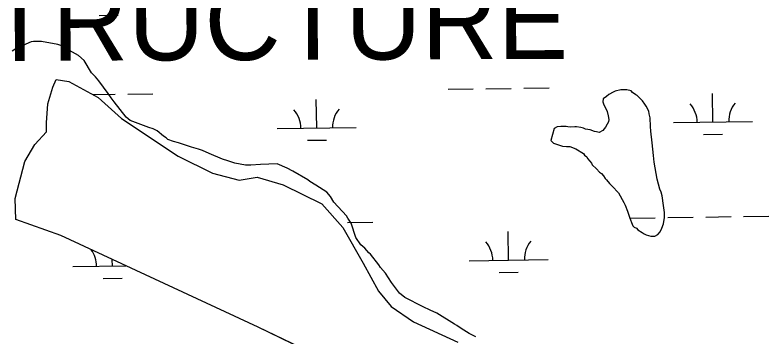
# Model space of a CAD drawing. Extents: x 3807117 to 3845308, y 337856 to 363736.
# Drawn here: x 3834347 to 3835302, y 345281 to 345688 of the extents above; entities that cross this region are included whole.
import ezdxf

# ---------------------------------------------------------------- set-up
doc = ezdxf.new("R2010")
doc.units = 0
for name, color, linetype in [('V-RIVR-IDEN', 7, 'Continuous'), ('V-SITE-VEGE', 7, 'Continuous'), ('V-TOPO-SHOR', 7, 'Continuous'), ('V-WETL-SWMP', 7, 'Continuous')]:
    doc.layers.add(name, color=color, linetype=linetype)

msp = doc.modelspace()

# ---------------------------------------------------------------- linework, layer by layer
at = {"layer": 'V-SITE-VEGE'}
for points in [[(3834698.71, 345490.65), (3834691.33, 345494.32), (3834678.88, 345499.83), (3834657.68, 345499.34), (3834645.69, 345498.4), (3834638.78, 345498.39), (3834625.41, 345500.67), (3834616.19, 345503.89), (3834609.73, 345505.72), (3834592.67, 345513.07), (3834584.36, 345516.74), (3834579.29, 345518.58), (3834570.53, 345520.87), (3834553.93, 345526.38), (3834547.47, 345528.21), (3834540.56, 345530.97), (3834538.25, 345532.8), (3834535.02, 345535.1), (3834526.71, 345541.54), (3834521.64, 345544.3), (3834516.1, 345546.14), (3834492.59, 345554.86), (3834487.51, 345559), (3834472.27, 345578.34), (3834468.58, 345583.4), (3834464.88, 345588.92), (3834452.87, 345605.04), (3834448.71, 345610.1), (3834443.64, 345615.16), (3834434.39, 345630.82), (3834427.01, 345637.26), (3834411.79, 345645.53), (3834407.17, 345648.75), (3834401.18, 345651.05), (3834380.43, 345654.7), (3834370.29, 345654.69), (3834367.07, 345654.22), (3834349.1, 345646.36), (3834343.12, 345642.66)], [(3834930.41, 345280.83), (3834922.1, 345285.42), (3834911.95, 345291.4), (3834906.42, 345295.54), (3834903.65, 345296.91), (3834881.04, 345311.17), (3834872.74, 345314.85), (3834863.98, 345318.98), (3834840.45, 345330.93), (3834833.99, 345336.45), (3834823.83, 345349.8), (3834815.98, 345361.77), (3834809.97, 345368.67), (3834807.66, 345372.36), (3834797.04, 345385.71), (3834795.2, 345387.55), (3834790.12, 345393.07), (3834785.04, 345397.67), (3834778.57, 345406.88), (3834772.55, 345424.85), (3834768.4, 345431.29), (3834766.55, 345434.06), (3834750.85, 345451.55), (3834746.23, 345458.45), (3834741.62, 345463.98), (3834727.77, 345473.18), (3834720.39, 345477.77), (3834717.62, 345479.61), (3834698.71, 345490.65)]]:
    msp.add_lwpolyline(points, dxfattribs=at)
msp.add_lwpolyline([(3835025.43, 345529.4), (3835029.12, 345526.18), (3835036.5, 345523.43), (3835040.19, 345522.51), (3835045.26, 345522.06), (3835049.41, 345522.06), (3835057.25, 345518.85), (3835066.94, 345512.87), (3835068.33, 345511.03), (3835071.09, 345508.73), (3835072.02, 345506.89), (3835074.79, 345503.2), (3835077.1, 345500.9), (3835078.02, 345498.6), (3835083.56, 345493.54), (3835087.25, 345489.4), (3835089.56, 345487.55), (3835092.33, 345484.79), (3835094.18, 345481.57), (3835096.03, 345479.73), (3835099.72, 345475.13), (3835103.41, 345471.91), (3835111.26, 345463.16), (3835118.19, 345451.19), (3835119.58, 345447.5), (3835122.82, 345440.13), (3835125.6, 345431.38), (3835128.38, 345423.55), (3835129.3, 345421.71), (3835131.15, 345419.87), (3835133.92, 345418.49), (3835135.76, 345416.65), (3835141.3, 345412.97), (3835143.61, 345411.59), (3835146.37, 345410.21), (3835152.37, 345408.38), (3835157.44, 345408.38), (3835161.12, 345410.69), (3835163.88, 345413.93), (3835166.18, 345418.54), (3835168.48, 345424.07), (3835169.39, 345431.91), (3835169.38, 345438.36), (3835168.44, 345447.12), (3835166.58, 345459.56), (3835165.19, 345464.16), (3835163.8, 345467.85), (3835160.09, 345480.75), (3835156.37, 345501.95), (3835155.44, 345510.7), (3835154.03, 345526.37), (3835152.16, 345541.12), (3835151.69, 345547.11), (3835151.22, 345558.17), (3835150.29, 345563.24), (3835149.82, 345566.47), (3835146.12, 345572.91), (3835144.74, 345575.67), (3835141.5, 345579.82), (3835135.04, 345586.26), (3835133.2, 345587.18), (3835129.04, 345590.4), (3835127.2, 345592.24), (3835121.66, 345593.61), (3835114.29, 345593.6), (3835106.92, 345591.75), (3835104.62, 345590.82), (3835099.09, 345587.59), (3835095.87, 345585.28), (3835091.72, 345582.05), (3835091.27, 345578.36), (3835092.19, 345576.06), (3835096.82, 345566.38), (3835098.21, 345560.85), (3835099.14, 345556.24), (3835098.68, 345553.02), (3835096.84, 345550.25), (3835095, 345546.56), (3835091.32, 345541.95), (3835086.72, 345539.63), (3835083.49, 345540.55), (3835080.72, 345541.01), (3835075.19, 345542.84), (3835069.66, 345543.76), (3835066.89, 345545.14), (3835063.66, 345546.05), (3835058.13, 345546.97), (3835055.83, 345546.96), (3835050.3, 345546.49), (3835047.07, 345546.95), (3835044.76, 345547.41), (3835038.31, 345547.4), (3835033.7, 345546.93), (3835029.56, 345544.62)], close=True, dxfattribs=at)
at = {"layer": 'V-TOPO-SHOR'}
msp.add_lwpolyline([(3834740.93, 345251.84), (3834654.87, 345293.38), (3834404.69, 345409.13), (3834347.92, 345429.43), (3834347, 345456.03), (3834359.34, 345503.03), (3834371.71, 345524.33), (3834386.76, 345540.31), (3834386.75, 345551.83), (3834388.48, 345575.77), (3834394.65, 345597.06), (3834399.07, 345606.82), (3834415.03, 345604.18), (3834452.3, 345583.85), (3834481.59, 345557.3), (3834553.48, 345509.54), (3834596.95, 345488.32), (3834630.65, 345479.51), (3834653.69, 345483.09), (3834686.51, 345473.39), (3834735.3, 345449.53), (3834761.95, 345419.43), (3834787.73, 345374.26), (3834807.28, 345338.82), (3834823.27, 345319.35), (3834851.67, 345299.89), (3834907.56, 345274.26)], dxfattribs=at)
at = {"layer": 'V-WETL-SWMP'}
for p, q in [((3834453.42, 345687.66), (3834477.42, 345688.02)), ((3834394.65, 345597.06), (3834399.07, 345606.82)), ((3834399.07, 345606.82), (3834415.03, 345604.18)), ((3834415.03, 345604.18), (3834452.3, 345583.85)), ((3834388.48, 345575.77), (3834394.65, 345597.06)), ((3834895.37, 345594.27), (3834927.37, 345594.75)), ((3834943.36, 345594.99), (3834975.36, 345595.47)), ((3834991.36, 345595.71), (3835023.35, 345596.19)), ((3834445.55, 345587.53), (3834473.51, 345587.95)), ((3834452.3, 345583.85), (3834481.59, 345557.3)), ((3834489.51, 345588.19), (3834521.5, 345588.67)), ((3834729.02, 345545.34), (3834728.48, 345581.34)), ((3835230.87, 345552.86), (3835230.33, 345588.86)), ((3834386.74, 345551.83), (3834388.48, 345575.77)), ((3834481.59, 345557.3), (3834553.48, 345509.53)), ((3835180.88, 345552.11), (3835280.87, 345553.61)), ((3834386.76, 345540.31), (3834386.74, 345551.83)), ((3834679.02, 345544.6), (3834779.01, 345546.09)), ((3834371.72, 345524.33), (3834386.76, 345540.31)), ((3835219.1, 345537.25), (3835243.1, 345537.61)), ((3834359.34, 345503.03), (3834371.72, 345524.33)), ((3834717.25, 345529.74), (3834741.25, 345530.09)), ((3834553.48, 345509.53), (3834596.95, 345488.32)), ((3834347, 345456.03), (3834359.34, 345503.03)), ((3834596.95, 345488.32), (3834630.65, 345479.51)), ((3834630.65, 345479.51), (3834653.69, 345483.09)), ((3834653.69, 345483.09), (3834686.51, 345473.39)), ((3834686.51, 345473.39), (3834735.3, 345449.53)), ((3834347.92, 345429.43), (3834347, 345456.03)), ((3834735.3, 345449.53), (3834761.95, 345419.43)), ((3834404.69, 345409.13), (3834347.92, 345429.43)), ((3835125.84, 345431.21), (3835157.83, 345431.68)), ((3835173.83, 345431.92), (3835205.83, 345432.4)), ((3835221.83, 345432.64), (3835253.82, 345433.12)), ((3835269.82, 345433.36), (3835301.82, 345433.84)), ((3834761.95, 345419.43), (3834787.72, 345374.26)), ((3834767.97, 345425.84), (3834799.97, 345426.32)), ((3834654.87, 345293.38), (3834404.69, 345409.13)), ((3834972.02, 345378.15), (3834971.48, 345414.15)), ((3834420.18, 345369.89), (3834487.34, 345370.89)), ((3834470.17, 345370.63), (3834470.05, 345378.89)), ((3834787.72, 345374.26), (3834807.28, 345338.82)), ((3834922.03, 345377.4), (3835022.02, 345378.9)), ((3834960.26, 345362.54), (3834984.25, 345362.9)), ((3834458.4, 345355.03), (3834482.4, 345355.38)), ((3834807.28, 345338.82), (3834823.27, 345319.35)), ((3834823.27, 345319.35), (3834851.67, 345299.89)), ((3834851.67, 345299.89), (3834907.56, 345274.26)), ((3834740.93, 345251.84), (3834654.87, 345293.38))]:
    msp.add_line(p, q, dxfattribs=at)
for centre, start, end in [((3835175.63, 345552.51), 0.08653, 41.63019), ((3835286.1, 345554.17), 140.08653, 181.63019), ((3834673.78, 345544.99), 0.08653, 41.63019), ((3834784.25, 345546.65), 140.08653, 181.63019), ((3834916.78, 345377.8), 0.08653, 41.63019), ((3835027.25, 345379.46), 140.08653, 181.63019), ((3834414.93, 345370.28), 0.08653, 36.62034)]:
    msp.add_arc(centre, 35.25, start, end, dxfattribs=at)

# ---------------------------------------------------------------- texts
at = {"layer": 'V-RIVR-IDEN'}
msp.add_text('STRUCTURE', height=100, rotation=0.21222, dxfattribs=at).set_placement((3834222.89, 345629.81))

doc.saveas('drawing.dxf')
